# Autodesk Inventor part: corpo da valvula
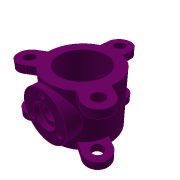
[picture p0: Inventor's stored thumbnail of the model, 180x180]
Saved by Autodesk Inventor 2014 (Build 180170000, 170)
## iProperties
Created: 2012-09
Part Number: corpo da valvula
Material: Generic
Document SubType Name: Modeling
Designer: TR-06
Density: 1 g/cm^3
Description: Item em estoque
Mass: 8967.88 g
Surface Area: 5777.29 cm^2
Volume: 8967.88 cm^3
Appearance: Magenta
Author: TR-06
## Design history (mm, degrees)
sketch "Sketch1"
  geometry: C1 r 97 at (0, 0); C2 r 140 at (0, 0); 1 further point
  constraints: 2 centre point, 2 coincident
  dimensions: "d0" = 194 diameter of C1; "d1" = 280 diameter of C2
extrude "Extrusion1" new body sketch "Sketch1" distance "d2" = 225; taper "d3" = 0 deg
sketch "Sketch2"
  geometry: L1 (-49.487, 167.857)-(-49.487, 130.962); L2 (49.487, 167.857)-(49.487, 130.962); C1 r 23.5 at (0, 175); A1 r 140 centre (0, 0) between (49.487, 130.962) and (-49.487, 130.962) reference; A2 r 50 centre (0, 175) between (49.487, 167.857) and (-49.487, 167.857)
  constraints: 4 end point, 4 point on circle, 2 centre point, 1 coincident, 1 parallel, 1 vertical
extrude "Extrusion2" join sketch "Sketch2" distance "d7" = 32; taper "d8" = 0 deg
pattern_circular "Circular Pattern1" dims angle "d10" = 360 deg
workplane "Work Plane1"
mirror "Mirror1"
workplane "Work Plane3"
sketch "Sketch3"
  geometry: L1 (-88.673, 193)-(-88.673, 225) reference; L2 (88.673, 225)-(-88.673, 225) reference; L3 (88.673, 225)-(88.673, 193) reference; L4 (88.673, 193)-(138.16, 193) reference; L5 (138.16, 193)-(138.16, 225) reference; L6 (49.487, 225)-(138.16, 225) reference; L7 (49.487, 225)-(49.487, 193) reference; L8 (49.487, 193)-(-49.487, 193) reference; L9 (-49.487, 193)-(-49.487, 225) reference; L10 (-138.16, 225)-(-49.487, 225) reference; L11 (-138.16, 225)-(-138.16, 193) reference; L12 (-138.16, 193)-(-88.673, 193) reference; L13 (-88.673, 0)-(-88.673, 32) reference; L14 (-88.673, 32)-(-138.16, 32) reference; L15 (-138.16, 32)-(-138.16, 0) reference; L16 (-49.487, 0)-(-138.16, 0) reference; L17 (-49.487, 0)-(-49.487, 32) reference; L18 (-49.487, 32)-(49.487, 32) reference; L19 (49.487, 32)-(49.487, 0) reference; L20 (138.16, 0)-(49.487, 0) reference; L21 (138.16, 0)-(138.16, 32) reference; L22 (138.16, 32)-(88.673, 32) reference; L23 (88.673, 32)-(88.673, 0) reference; L24 (-88.673, 0)-(88.673, 0) reference; L25 (0, 225)-(0, 0); C1 r 100 at (0, 112.5)
  constraints: 2 end point, 2 midpoint, 1 centre point, 1 perpendicular
  dimensions: "d15" = 200 diameter of C1
extrude "Extrusion3" join sketch "Sketch3" stored distance "d16" = 32; taper "d17" = 0 deg
sketch "Sketch4"
  geometry: C1 r 100 at (0, 0) reference; C2 r 28.1 at (0, 0); C3 r 50 at (0, 0); 1 further point
  constraints: 2 centre point, 2 coincident
  dimensions: "d18" = 56.2 diameter of C2; "d19" = 100 diameter of C3
extrude "Extrusion4" cut sketch "Sketch4" distance "d20" = 20; taper "d21" = 0 deg
sketch "Sketch6"
  geometry: C1 r 10.15 at (0, 75); 1 further point
  constraints: 1 centre point
  dimensions: "d26" = 20.3 diameter of C1
extrude "Extrusion6" cut sketch "Sketch6" distance "d27" = 15; taper "d28" = 0 deg
pattern_circular "Circular Pattern2" dims angle "d30" = 360 deg
workplane "Work Plane4"
sketch "Sketch7"
  geometry: L1 (49.487, 32)-(49.487, 0) reference; L2 (138.16, 0)-(49.487, 0) reference; L3 (138.16, 0)-(138.16, 32) reference; L4 (138.16, 32)-(88.673, 32) reference; L5 (88.673, 32)-(88.673, 0) reference; L6 (-88.673, 0)-(88.673, 0) reference; L7 (-88.673, 0)-(-88.673, 32) reference; L8 (-88.673, 32)-(-138.16, 32) reference; L9 (-138.16, 32)-(-138.16, 0) reference; L10 (-49.487, 0)-(-138.16, 0) reference; L11 (-49.487, 0)-(-49.487, 32) reference; L12 (-49.487, 32)-(49.487, 32) reference; L13 (49.487, 225)-(49.487, 193) reference; L14 (49.487, 193)-(-49.487, 193) reference; L15 (-49.487, 193)-(-49.487, 225) reference; L16 (-138.16, 225)-(-49.487, 225) reference; L17 (-138.16, 225)-(-138.16, 193) reference; L18 (-138.16, 193)-(-88.673, 193) reference; L19 (-88.673, 193)-(-88.673, 225) reference; L20 (88.673, 225)-(-88.673, 225) reference; L21 (88.673, 225)-(88.673, 193) reference; L22 (88.673, 193)-(138.16, 193) reference; L23 (138.16, 193)-(138.16, 225) reference; L24 (49.487, 225)-(138.16, 225) reference; L25 (0, 225)-(0, 0); C1 r 37.5 at (0, 112.5); 1 further point
  constraints: 2 end point, 2 midpoint, 1 centre point, 1 perpendicular, 1 other
  dimensions: "d33" = 75 diameter of C1
extrude "Extrusion7" join sketch "Sketch7" stored distance "d34" = 15; taper "d35" = 0 deg
workplane "Work Plane5"
sketch "Sketch9"
  geometry: C1 r 100 at (0, 0) reference; 2 further points
  constraints: 1 coincident
hole "Hole1" sketch "Sketch9" at (0, 0) diameter "d36" = 56.2; stored, may be unused: countersink angle "d40" = 90 deg, drill point angle "d42" = 130 deg; dims "d37" = 6, "d38" = 4, "d39" = 2, "d41" = 310
body "Solid1"
node "Projected Loop1"
node "Projected Loop2"
other parameters: "d12" = -112.5, "d32" = 165
